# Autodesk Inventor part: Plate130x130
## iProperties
Created: 2006-01
Part Number: Plate130x130
Document SubType Name: Modeling
Designer: Administrator
Mass: 169 g
Surface Area: 390 cm^2
Volume: 169 cm^3
Density: 1 g/cm^3
CSToolsMass: 0.2
CSToolsVolume: 169000.0
CSToolsArea: 390.0
Author: Administrator
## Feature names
1. Extrusion1
